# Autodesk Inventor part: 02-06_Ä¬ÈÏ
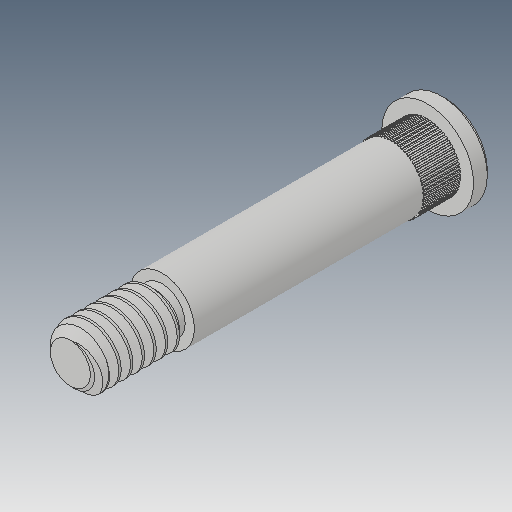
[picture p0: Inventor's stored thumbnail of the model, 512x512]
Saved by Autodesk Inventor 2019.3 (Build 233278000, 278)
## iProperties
Created: 2010-06
Part Number: 02-06_Ä¬ÈÏ
Material: Ogólny
Document SubType Name: Modeling
Designer: CADENGINEERING4
Density: 1 g/cm^3
Appearance: Domyślna
Author: CADENGINEERING4
Revision Number: ÈÎºÎ
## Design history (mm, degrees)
feature "NONE"
node "Bryła1"
